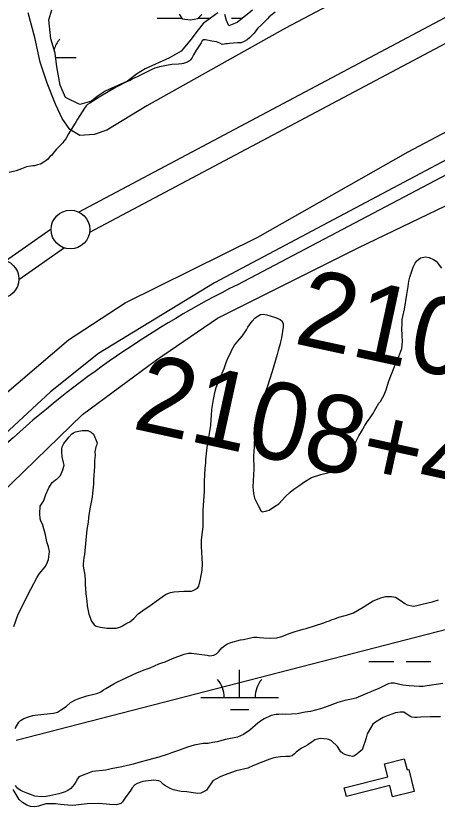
# Model space of a CAD drawing. Extents: x 3245246 to 3283090, y 806824 to 832173.
# Drawn here: x 3259157 to 3259701, y 817056 to 818083 of the extents above; entities that cross this region are included whole.
import ezdxf

# ---------------------------------------------------------------- set-up
doc = ezdxf.new("R2010")
doc.units = 0
for name, color, linetype in [('V-BLDG-OTLN', 7, 'Continuous'), ('V-LEVE-TOET', 7, 'Continuous'), ('V-ROAD-CNTR', 7, 'Continuous'), ('V-SITE-VEGE', 7, 'Continuous'), ('V-SURV-IDEN', 7, 'Continuous'), ('V-SURV-LINE', 7, 'Continuous'), ('V-TOPO-SHOR', 7, 'Continuous'), ('V-WETL-SWMP', 7, 'Continuous')]:
    doc.layers.add(name, color=color, linetype=linetype)

msp = doc.modelspace()

# ---------------------------------------------------------------- linework, layer by layer
at = {"layer": 'V-BLDG-OTLN'}
msp.add_lwpolyline([(3259633.5, 817116.1), (3259658.9, 817122.6), (3259662.5, 817108.4), (3259664.7, 817108.9), (3259671.9, 817080.3), (3259643.9, 817073.2), (3259640.1, 817088), (3259584.2, 817073.8), (3259581.4, 817084.9), (3259637.8, 817099.2)], close=True, dxfattribs=at)
at = {"layer": 'V-LEVE-TOET'}
for points in [[(3259614.2, 818124.6), (3259505.3, 818066.7), (3259326.6, 817966.3), (3259274.9, 817934.8), (3259258.3, 817929.2), (3259239.7, 817928), (3259226.9, 817935.9), (3259217.1, 817949.9), (3259208.5, 817968.5), (3259197.7, 817995.8), (3259188.4, 818022.8), (3259181.9, 818054.7), (3259173.3, 818086.8)], [(3259139.6, 817590.7), (3259225.1, 817663.9), (3259298.4, 817711.9), (3259469.9, 817796.8), (3259663.9, 817906.9), (3259863.5, 818012.7), (3259897.5, 818027), (3259915.9, 818038.3), (3259933.7, 818053.8), (3259958.5, 818072.4), (3259984.6, 818087.4)]]:
    msp.add_lwpolyline(points, dxfattribs=at)
at = {"layer": 'V-ROAD-CNTR'}
msp.add_lwpolyline([(3260054.1, 818057.4), (3259889.8, 817970.3), (3259443.4, 817735.3)], dxfattribs=at)
msp.add_arc((3260034.1, 816558.9), 1316.4, 116.6623, 132.47, dxfattribs=at)
at = {"layer": 'V-SITE-VEGE'}
for points in [[(3259492, 818087.6), (3259484.3, 818081.4), (3259482.1, 818078.9), (3259478.2, 818075.1), (3259474.4, 818071.2), (3259469.5, 818066.2), (3259464.9, 818060.4), (3259462.2, 818057.5), (3259459, 818054.2)], [(3259459, 818054.2), (3259455.9, 818051.9), (3259452.3, 818049.4), (3259448.4, 818047.9), (3259443.5, 818047.9), (3259433.2, 818047.2), (3259430.8, 818046.7), (3259428.3, 818046.7), (3259426.1, 818046), (3259423.8, 818045.8), (3259420.5, 818047.6), (3259416.2, 818049), (3259410.4, 818050), (3259402.2, 818051.9), (3259399.8, 818051.9), (3259397.9, 818050.4), (3259396.5, 818048), (3259389.7, 818037.6), (3259386.6, 818032.5), (3259384.4, 818027.9), (3259383, 818026.1), (3259381.6, 818024.6), (3259378.8, 818023), (3259373.9, 818021.3), (3259371.4, 818020.8), (3259367.3, 818020.4), (3259358.7, 818019.7), (3259342.7, 818016.8), (3259336.8, 818015.1), (3259332.9, 818013.4), (3259313.8, 818003.8), (3259308, 818001.2), (3259304.8, 817999.4), (3259300.1, 817997.3), (3259287.7, 817991.2), (3259283.6, 817988.7), (3259278.5, 817985.9), (3259265, 817977.8), (3259252.8, 817969.9), (3259249.6, 817968), (3259248.2, 817966.5), (3259245.9, 817963.4), (3259236.9, 817949.4), (3259235.1, 817946.1), (3259229.4, 817937.2), (3259225.4, 817930.2), (3259221.6, 817923.6), (3259219.3, 817920.9), (3259217.7, 817918.6), (3259209.4, 817909.9), (3259205.4, 817905.2), (3259203.5, 817902.9), (3259201.7, 817901.2), (3259198.1, 817897.3), (3259193.4, 817893.7), (3259191.2, 817892.5), (3259188.9, 817891.2), (3259185.2, 817890.2), (3259181.4, 817889.1), (3259179.3, 817888.7), (3259176.4, 817888.4), (3259171.1, 817887.5), (3259166.6, 817885.9), (3259164.4, 817885.2), (3259161.1, 817883.9), (3259157.6, 817882.3), (3259148.4, 817880.1)], [(3259455.2, 817677), (3259457, 817680.3), (3259462.5, 817688.2), (3259465.9, 817692.1), (3259469, 817694.2), (3259473.4, 817696.7), (3259476.5, 817697.4), (3259481.6, 817696.4), (3259492.6, 817693), (3259498.5, 817690.2), (3259500.6, 817688.6), (3259502.5, 817684.7), (3259502.7, 817680.6), (3259500.4, 817666.5), (3259498.9, 817661.3), (3259498.5, 817658.9), (3259496.1, 817650.2), (3259494.7, 817644.9), (3259488.4, 817623.1), (3259481.7, 817602.7), (3259476.7, 817589.3), (3259473.5, 817580.2), (3259469, 817566.5), (3259467.8, 817561.9), (3259467, 817558), (3259466.8, 817553.3), (3259466.9, 817547.6), (3259465.4, 817535.2), (3259465, 817531.3), (3259464.9, 817525.8), (3259464.4, 817519.2), (3259464.2, 817513.9), (3259464.4, 817497.1), (3259463.2, 817474.1), (3259464.3, 817465.3), (3259465.6, 817459.4), (3259470.1, 817450), (3259474, 817442.4), (3259475.9, 817441.6), (3259481.6, 817442.9), (3259484.5, 817443.8), (3259491.4, 817448.8), (3259496.7, 817452.1), (3259505.6, 817461.5), (3259511.7, 817467.3), (3259516.4, 817471), (3259523.9, 817476.2), (3259529.2, 817480.2), (3259539, 817486.2), (3259551, 817490.1), (3259560, 817492), (3259572.1, 817496.2), (3259577, 817499.2), (3259587.7, 817510), (3259590.7, 817518.6), (3259593.9, 817526.6), (3259596.1, 817531.4), (3259600.3, 817540), (3259604.9, 817547.7), (3259605.7, 817549.5), (3259607.5, 817552.6), (3259611.2, 817558), (3259614.2, 817562.1), (3259618.4, 817568.5), (3259626.1, 817582), (3259628.1, 817584.4), (3259632.9, 817593.1), (3259635.7, 817599.3), (3259638.7, 817609.6), (3259642.5, 817619.7), (3259649, 817636.1), (3259652, 817642.7), (3259653.2, 817646), (3259655.6, 817652.8), (3259656.5, 817661.7), (3259656.2, 817669.6), (3259655.9, 817678.5), (3259656.1, 817684), (3259656.4, 817690.2), (3259657.2, 817694.3), (3259659.3, 817703.7), (3259662.4, 817722.6), (3259663.9, 817733.1), (3259664.7, 817739.7), (3259666.1, 817745.2), (3259668.8, 817752.8), (3259670.4, 817757.8), (3259672.8, 817763.1), (3259675.1, 817766), (3259680.1, 817769.8), (3259686.5, 817771.5), (3259691, 817770.3), (3259696.6, 817767.7), (3259700.1, 817765.7), (3259706.9, 817756.7)], [(3259218.9, 817505.6), (3259216.9, 817513), (3259216.4, 817519.5), (3259216.4, 817522.8), (3259217.2, 817525.7), (3259219.2, 817530.2), (3259226.1, 817538.7), (3259229.5, 817542.6), (3259231.5, 817543.9), (3259234.2, 817545.2), (3259242.8, 817546.7), (3259246.9, 817546.9), (3259250.2, 817546.8), (3259254.5, 817544.8), (3259257.4, 817542.3), (3259262.4, 817531.1), (3259261.5, 817527.6), (3259260.7, 817525.8), (3259259.3, 817519.4), (3259259.6, 817514.9), (3259259, 817507.9), (3259258.7, 817500.3), (3259257.5, 817482.9), (3259257.5, 817477.7), (3259256, 817465.8), (3259255.6, 817460.7), (3259252.7, 817445.5), (3259251.2, 817434.4), (3259250.5, 817428.5), (3259248.9, 817418.8), (3259247.5, 817405.2), (3259246, 817386.8), (3259245.2, 817382.7), (3259244.3, 817374), (3259244.3, 817371.6), (3259246.1, 817359.7), (3259246.6, 817352.9), (3259246.7, 817348.2), (3259247.4, 817335.9), (3259248.8, 817326.1), (3259249.4, 817320.2), (3259251.6, 817309.5), (3259255, 817300.5), (3259258.3, 817295.5), (3259261, 817294.1), (3259266.6, 817292.5), (3259274.6, 817291.3), (3259286.9, 817291.3), (3259291.4, 817292.5), (3259294.8, 817294.6), (3259300.7, 817297.8), (3259304.4, 817299.7), (3259309.5, 817304), (3259315.4, 817309.8), (3259321.3, 817314.2), (3259327, 817318.2), (3259329, 817319.4), (3259338.4, 817326.1), (3259349.1, 817334.2), (3259351.4, 817335.3), (3259357.1, 817337.6), (3259361.4, 817338.4), (3259367.8, 817338.7), (3259374.3, 817339), (3259383.9, 817339.1), (3259386.4, 817340), (3259391.7, 817343.1), (3259393.7, 817345.6), (3259395.9, 817354.8), (3259398, 817366.5), (3259398.1, 817374.7), (3259396.8, 817397.1), (3259397.1, 817405.5), (3259399.2, 817422.5), (3259399, 817443.9), (3259401, 817468.3), (3259401, 817481.4), (3259401.9, 817497.8), (3259402.4, 817505.2), (3259402.5, 817509.1), (3259404.2, 817524.9), (3259406.1, 817535.2), (3259409.2, 817553.5), (3259409.5, 817561.5), (3259409.9, 817566.2), (3259410.2, 817573.8), (3259412.5, 817587.1), (3259414.7, 817597.6), (3259416.1, 817602.4), (3259417.6, 817606.7), (3259420.6, 817614.1), (3259426.2, 817627.1), (3259429, 817634.7), (3259431.6, 817641.3), (3259434.6, 817646.9), (3259436.4, 817651), (3259439.6, 817657), (3259444.1, 817662.3), (3259449.6, 817668.8), (3259451, 817670.4), (3259455.2, 817677)], [(3259154.4, 817293.5), (3259160.1, 817309.5), (3259176.4, 817341.9), (3259184.6, 817357.4), (3259187.9, 817362.1), (3259194.9, 817370.8), (3259197.4, 817374.7), (3259199.3, 817380.3), (3259200.5, 817390.6), (3259199.2, 817396.5), (3259197.2, 817403), (3259196.2, 817407.5), (3259195.3, 817412.2), (3259192.1, 817424.5), (3259189.3, 817430.2), (3259188.7, 817432.9), (3259188, 817439.4), (3259188.7, 817448.9), (3259190.5, 817451.6), (3259192.8, 817455.7), (3259193.6, 817457.5), (3259195.9, 817464.1), (3259199.7, 817472.6), (3259204.2, 817479.6), (3259208.2, 817482.9), (3259210.1, 817484), (3259213.3, 817486.9), (3259214.7, 817488.8), (3259217.7, 817496.2), (3259219.5, 817502.1), (3259218.9, 817505.6)], [(3259705.7, 817177), (3259700.7, 817176.8), (3259696.2, 817176.9), (3259692.3, 817176.7), (3259679.8, 817176.5), (3259675.5, 817176.1), (3259672.4, 817176), (3259668.5, 817176.4), (3259666.1, 817177.6), (3259661.3, 817180.8), (3259658.2, 817182.7), (3259655.8, 817183), (3259653.5, 817183), (3259647.4, 817181.9), (3259638.2, 817178.5), (3259631.8, 817176), (3259621.9, 817170.1), (3259618.4, 817167.2), (3259612.2, 817156.9), (3259611.2, 817154.6), (3259609.8, 817149.5), (3259607.8, 817144.2), (3259606.8, 817140.7), (3259604.4, 817134.3), (3259600.8, 817131), (3259597.5, 817128.5), (3259594.5, 817126.4), (3259592.2, 817125.7), (3259588.3, 817126.3), (3259582.3, 817128.3), (3259579.3, 817129.9), (3259577.2, 817131.7), (3259572.8, 817138.4), (3259564.9, 817145.7), (3259561.4, 817147.3), (3259559.2, 817147.9), (3259554.9, 817148.5), (3259550.3, 817148.6), (3259543.6, 817146.9), (3259541.1, 817145.5), (3259538.7, 817143.6), (3259534.4, 817140.7), (3259531.2, 817139), (3259526.1, 817136.1), (3259519.4, 817131.1), (3259517.1, 817129), (3259514.1, 817126.5), (3259510.6, 817125.4), (3259506.1, 817125.4), (3259499.1, 817125.3), (3259493, 817124.4)], [(3259493, 817124.4), (3259489.3, 817123.3), (3259485.4, 817121.9), (3259473, 817117.4), (3259466.6, 817114.9), (3259464.2, 817114), (3259456.8, 817110.5), (3259441.7, 817107), (3259426.2, 817101.3), (3259420.9, 817099.4), (3259411.7, 817094), (3259403.6, 817082), (3259399.8, 817079.7), (3259396.3, 817078.2), (3259391.8, 817077.7), (3259378, 817079.8), (3259370.7, 817080.4), (3259366.5, 817081), (3259361, 817082.3), (3259356.5, 817084.3), (3259350.3, 817087.7), (3259347.8, 817089.4), (3259343.9, 817093), (3259341.8, 817094.2), (3259335.6, 817095), (3259321.3, 817093.4), (3259313.9, 817090.8), (3259310.9, 817088.7), (3259307.6, 817085.2), (3259304.8, 817080.7), (3259299.4, 817073.6), (3259296.5, 817069.5), (3259295.1, 817066.8), (3259292.9, 817064.7), (3259287.4, 817063.2), (3259278.8, 817063.6), (3259274.3, 817064.1), (3259269.1, 817064.5), (3259263.6, 817064.6), (3259249.4, 817064.5), (3259230.6, 817062.2), (3259224.2, 817062.7), (3259214.8, 817063.3), (3259208.2, 817064.4), (3259196.1, 817064.5), (3259186.3, 817061.3), (3259181.8, 817060.6), (3259175.9, 817060.8), (3259171.5, 817062.6), (3259168, 817064.6), (3259165.8, 817066.2), (3259161.6, 817070), (3259153.7, 817082.9)]]:
    msp.add_lwpolyline(points, dxfattribs=at)
at = {"layer": 'V-SURV-LINE'}
for points in [[(3259238.3, 817829.2), (3260394.8, 818443.8)], [(3260408.9, 818417.3), (3259252.3, 817802.7)], [(3259144, 817766.3), (3259202.7, 817807.4)], [(3259219.9, 817782.8), (3259161.2, 817741.7)]]:
    msp.add_lwpolyline(points, dxfattribs=at)
for centre in [(3259227.7, 817806.6), (3259136.2, 817742.6)]:
    msp.add_circle(centre, 25, dxfattribs=at)
at = {"layer": 'V-TOPO-SHOR'}
for points in [[(3260152.6, 818148.3), (3259812.1, 817949.2), (3259413.6, 817737.7), (3259264.1, 817646.5), (3259201.8, 817596.7), (3259035.7, 817443.2), (3258545.8, 817011.7), (3258321.5, 816825.1), (3257956.1, 816493.2), (3257545.1, 816115.6), (3257225.3, 815833.5), (3257084.2, 815704.9), (3257013.6, 815651), (3256897.3, 815568), (3256357.6, 815240.4)], [(3259106.3, 817434.9), (3259243.3, 817567.6), (3259338.8, 817638.1), (3259417.7, 817692.1), (3259600.4, 817783.3), (3259712.4, 817837.2)], [(3259157.6, 817146.5), (3260314.5, 817445.1), (3260992.7, 817604.4)]]:
    msp.add_lwpolyline(points, dxfattribs=at)
at = {"layer": 'V-WETL-SWMP'}
for p, q in [((3259339.8, 818079.7), (3259371.6, 818079.7)), ((3259392.8, 818079.7), (3259408.6, 818079.7)), ((3259435.8, 818079.7), (3259449.9, 818079.7)), ((3259208.7, 818029), (3259235.2, 818029)), ((3259613.3, 817248.1), (3259645.3, 817248.1)), ((3259661.3, 817248.1), (3259693.3, 817248.1)), ((3259446.3, 817201.7), (3259446.3, 817237.7)), ((3259396.3, 817201.8), (3259496.3, 817201.7)), ((3259434.3, 817186.3), (3259458.3, 817186.3))]:
    msp.add_line(p, q, dxfattribs=at)
for points in [[(3259417.9, 818086.6), (3259399.2, 818072.7), (3259392.5, 818064.8), (3259381.8, 818050.6), (3259370.9, 818037.1), (3259355.8, 818028.5), (3259324.4, 818014.4), (3259313.2, 818007.3), (3259301.4, 817998.2), (3259272.4, 817985.6), (3259262.1, 817978.7), (3259254.7, 817972.6), (3259239.8, 817968), (3259221.5, 817977.2), (3259214.3, 817993.3), (3259210.2, 818016.8), (3259208.1, 818034.5), (3259202.2, 818053.1), (3259200, 818077.4), (3259203.8, 818090.4)], [(3259368, 818084.8), (3259372.1, 818078.9), (3259382.8, 818077.4), (3259392.4, 818079.4), (3259397.5, 818084.5)], [(3259462.8, 818090), (3259443.1, 818074.2), (3259432.3, 818070), (3259429.3, 818076.9), (3259427.2, 818084.3)], [(3259345.6, 817246.6), (3259349.9, 817247.9), (3259359.5, 817252.1), (3259374.4, 817257.6), (3259380.3, 817258.9), (3259384, 817259.2), (3259404.3, 817256.5), (3259407.6, 817255.7), (3259413, 817256.4), (3259416.2, 817258.3), (3259419.5, 817261.4), (3259423.3, 817265.8), (3259427, 817268.9), (3259430.4, 817271), (3259434.9, 817272.7), (3259447.4, 817276.1), (3259451.3, 817276.7), (3259458.4, 817278.5), (3259464.8, 817279.8), (3259468.9, 817279.6), (3259472, 817279.2), (3259477.7, 817278.9), (3259485.9, 817278.6), (3259494.1, 817279.1), (3259500.7, 817280.6), (3259510.1, 817284.4), (3259518, 817287.1), (3259524.2, 817288.6), (3259528.4, 817289.9), (3259532.3, 817290.8), (3259555.2, 817298.4), (3259559.1, 817299.9), (3259562.2, 817300.7), (3259565.8, 817302.4), (3259569.1, 817303.3), (3259574.2, 817305.4), (3259580.9, 817307.3), (3259584.2, 817308), (3259593.4, 817311.1), (3259606, 817318.5), (3259611.9, 817322.6), (3259618.9, 817326.6), (3259628.5, 817330.6), (3259634.8, 817332.1), (3259642.6, 817332.2), (3259647.7, 817331.4), (3259655, 817326.8), (3259659.7, 817323.2), (3259662.6, 817321.6), (3259671, 817319.6), (3259675.1, 817320.5), (3259681.9, 817322.4), (3259694.8, 817325.4), (3259703.1, 817328)], [(3259156.5, 817161.9), (3259160.9, 817169.7), (3259163.1, 817172), (3259167.4, 817174.5), (3259173.5, 817177), (3259179.2, 817178.5), (3259182.3, 817178.8), (3259185.6, 817179.4), (3259193.4, 817180.1), (3259205.9, 817181.7), (3259211.2, 817183), (3259214.9, 817185.3), (3259222.2, 817190.3), (3259227.7, 817195.1), (3259234.4, 817198.8), (3259238.5, 817200.5), (3259248.7, 817204.1), (3259258.1, 817205.9), (3259263, 817207.2), (3259267.1, 817209.3), (3259270.5, 817211.8), (3259273.4, 817213.2), (3259283.8, 817219.3), (3259287.7, 817221.4), (3259314.4, 817234), (3259324.2, 817237.8), (3259330.9, 817239.9), (3259341.9, 817245.2), (3259345.6, 817246.6)], [(3259708.9, 817220), (3259688.6, 817216.7), (3259683.5, 817216.2), (3259678.1, 817216.1), (3259665.4, 817217), (3259657, 817217.9), (3259645.9, 817220.3), (3259641.8, 817220.4), (3259638.1, 817219.6), (3259625.1, 817213.1), (3259619.8, 817210.8), (3259615.9, 817209.3), (3259611.6, 817207.2), (3259596.5, 817201.1), (3259593, 817200), (3259582.2, 817197.8), (3259573.2, 817195.1), (3259559.5, 817190), (3259550.7, 817187), (3259538, 817183.8), (3259531.1, 817182.7), (3259520.6, 817180.7), (3259513.3, 817180.2), (3259505.7, 817179.9), (3259502, 817180.1), (3259496.7, 817180), (3259493.4, 817179.6), (3259487, 817178.3), (3259477.9, 817174.3), (3259474.4, 817172.2), (3259469.7, 817168.7), (3259459.6, 817159.7), (3259451.2, 817154.1), (3259443.3, 817150.7), (3259428.1, 817147.3), (3259417.1, 817144.3), (3259411.2, 817143.4), (3259405.8, 817142.3), (3259399.3, 817142.2), (3259387.4, 817140.1), (3259379, 817137.7), (3259367.4, 817133.1), (3259358.4, 817130.1), (3259354.1, 817128.4), (3259341.8, 817124.8), (3259327.3, 817120.7), (3259321, 817119.2), (3259313, 817116.7), (3259308.7, 817115.8), (3259305.3, 817114.7), (3259294.2, 817112.2), (3259280.5, 817109.7), (3259273.6, 817108)], [(3259273.6, 817108), (3259256.1, 817106), (3259238.4, 817099.4), (3259237, 817096.5), (3259234.6, 817092.8), (3259232.5, 817089.3), (3259228.1, 817084.1), (3259224.2, 817081.6), (3259221, 817080), (3259215.6, 817078.1), (3259212.6, 817077.2), (3259200.9, 817074.6), (3259196, 817073.7), (3259190.9, 817073.5), (3259181.9, 817074.4), (3259172.6, 817077.6), (3259166.4, 817080.2), (3259162.9, 817082), (3259158.4, 817085.2), (3259156.9, 817088.1)]]:
    msp.add_lwpolyline(points, dxfattribs=at)
for centre, start, end in [((3259240.4, 818029.5), 139.2032, 163.8913), ((3259391, 817202.2), 359.2032, 40.7468), ((3259501.5, 817202.2), 139.2032, 180.7468)]:
    msp.add_arc(centre, 35.2, start, end, dxfattribs=at)

# ---------------------------------------------------------------- texts
at = {"layer": 'V-SURV-IDEN'}
for s, rotation, p in [('2109+59.0', 347.8062, (3259514.6, 817659.8)), ('2108+47.4', 347.6335, (3259305.8, 817549.8))]:
    msp.add_text(s, height=100, rotation=rotation, dxfattribs=at).set_placement(p)

doc.saveas('drawing.dxf')
